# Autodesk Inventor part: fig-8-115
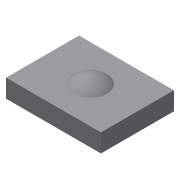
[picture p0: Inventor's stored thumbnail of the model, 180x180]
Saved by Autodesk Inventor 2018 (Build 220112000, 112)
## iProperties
Created: 2009-09
Part Number: fig-8-115
Document SubType Name: Modeling
Designer: Sham
Density: 1 g/cm^3
Material: Generic
Appearance: Default
Author: Sham
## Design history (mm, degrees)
sketch "Sketch1"
  geometry: L1 (-26, 20)-(0, 20); L2 (0, 20)-(0, 0); L3 (0, 0)-(-26, 0); L4 (-26, 0)-(-26, 20)
  constraints: 8 end point, 2 parallel, 1 horizontal, 1 perpendicular
extrude "Extrusion1" new body sketch "Sketch1" distance "d0" = 5; taper "d1" = 0 deg
workplane "Work Plane1"
feature "Sculpt2"
body "Solid1"
sketch "Sketch2"
  geometry: L1 (13, 8)-(13, 5); A1 r 7.517 centre (12.377, -0.349) between (17.658, 5) and (13, 7.142)
  constraints: 2 end point, 2 point on circle, 1 centre point
body "Srf2"
feature "RevolutionSrf2" dims angle "d4" = 90 deg
